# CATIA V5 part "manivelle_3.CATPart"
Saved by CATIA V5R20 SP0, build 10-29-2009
Part number: manivelle_3
Bounding box of the stored display mesh (mm): x 0 to 10, y -110 to 10, z 40 to 60
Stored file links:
  D:\Dropbox\IAO_2011\MMS_GR2\IAO_2011_1491_mcabanel\IAO_2011_1491_mcabanel\manivelle_3.CATPart
  U:\2A\IAO\Projet\ass\kin\IAO_mcabanel.CATProduct
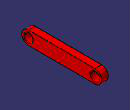
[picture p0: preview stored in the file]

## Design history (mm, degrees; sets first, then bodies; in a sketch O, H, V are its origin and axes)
Set1
  Point1: linked copy from another document
  Point2: linked copy from another document
Body1 (main body)
  Sketch1 on yz-plane, origin (0, 0, 0), H (0, 1, 0), V (0, 0, 1)
    construction line L1 (0, 50) -> (-100, 50)
    point P1 (0, 50)
    point P2 (-100, 50)
    line L2 (0, 40) -> (-100, 40)
    line L3 (-100, 60) -> (0, 60)
    arc A1 centre (-100, 50) radius 10 from (-100, 40) to (-100, 60) cw
    arc A2 centre (0, 50) radius 10 from (0, 60) to (0, 40) cw
    reference projected point E1 (-100, 50) from Point1
    reference projected point E2 (0, 50) from Point2
    circle A3 centre (0, 50) radius 7
    point P7 (0, 50)
    circle A4 centre (-100, 50) radius 7
    point P8 (-100, 50)
    reference projected point E3 (-100, 50) from Point1
    reference projected point E4 (0, 50) from Point2
    distance L1 L2 = 10
    radius A4 = 7
    radius A3 = 7
    horizontal: L1 H
    tangency: A1 L2, A2 L2, A1 L3, A2 L3
    coincidence: P2 E1, P1 E2, P8 E3, P7 E4
  Pad1: profile Sketch1, direction (1, 0, 0), length 10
